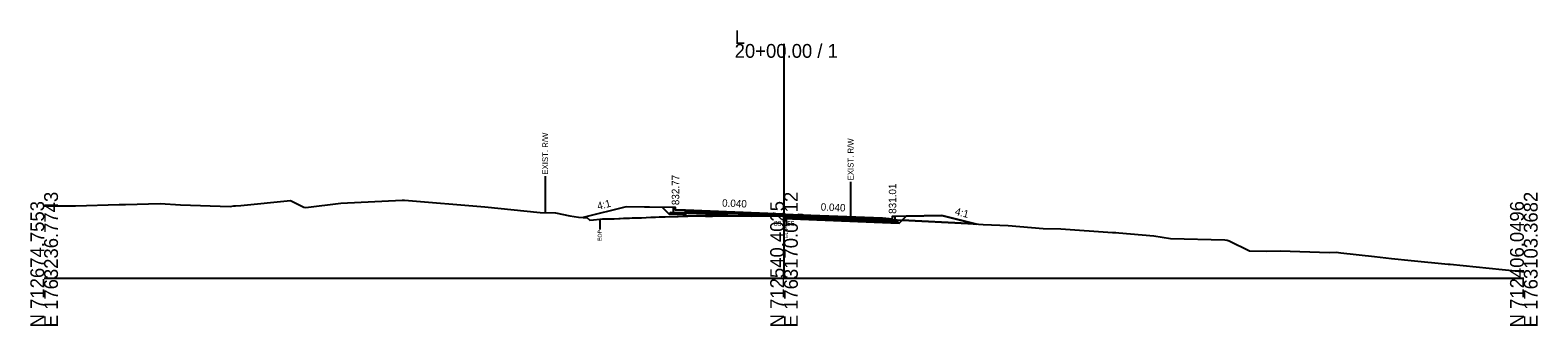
# Model space of a CAD drawing. Extents: x -26 to 5303, y -10 to 9578.
# Drawn here: x 997.2 to 1302.8, y -9.7 to 50.2 of the extents above; entities that cross this region are included whole.
import ezdxf

# ---------------------------------------------------------------- set-up
doc = ezdxf.new("R2010")
doc.units = 0
for name, color, linetype in [('Default', 7, 'Continuous'), ('Exist CMT Pavement', 7, 'Continuous'), ('Exist Cross Section Cell', 7, 'Continuous'), ('Exist XS Ground Line', 7, 'Continuous'), ('Old_Level_10', 7, 'Continuous'), ('Old_Level_3', 7, 'Continuous'), ('Prop CMT Conc Surface', 7, 'Continuous'), ('Prop CMT Concrete Structures', 7, 'Continuous'), ('Prop CMT Pvmt Course 1', 7, 'Continuous'), ('Prop CMT Pvmt Course 1 CG', 7, 'Continuous'), ('Prop CMT Pvmt Course 2', 7, 'Continuous'), ('Prop CMT Pvmt Course 3', 7, 'Continuous'), ('Prop CMT Pvmt Surface', 7, 'Continuous'), ('Prop CMT Slope Grass', 7, 'Continuous'), ('Prop CMT Subgrade Earthwork', 7, 'Continuous'), ('Prop XS Earthwork Shape', 7, 'Continuous'), ('Prop XS Hydro Elevations', 7, 'Continuous'), ('Prop XS SE Text', 7, 'Continuous'), ('Prop XS Side Slope Text', 7, 'Continuous'), ('Prop XS Wedging', 7, 'Continuous')]:
    doc.layers.add(name, color=color, linetype=linetype)

msp = doc.modelspace()

# ---------------------------------------------------------------- linework, layer by layer
at = {"layer": 'Exist CMT Pavement'}
msp.add_lwpolyline([(1130, 12.53), (1130.48, 12.54), (1132.31, 12.58), (1134.1, 12.56), (1135.1, 12.54), (1135.43, 12.56), (1137.44, 12.62), (1138.15, 12.6), (1138.52, 12.61), (1139.23, 12.61), (1139.77, 12.61), (1140.68, 12.6), (1141.73, 12.59), (1142.89, 12.58), (1143.47, 12.57), (1145.19, 12.6), (1146.26, 12.6), (1147.35, 12.6), (1149.05, 12.58), (1150, 12.55)], dxfattribs=at)
at = {"layer": 'Exist Cross Section Cell'}
for p, q in [((1150, 0), (1150, 47.44)), ((1000, 0), (1150, 0)), ((1150, 0), (1300, 0))]:
    msp.add_line(p, q, dxfattribs=at)
at = {"layer": 'Exist XS Ground Line'}
msp.add_lwpolyline([(1000, 14.61), (1006.38, 14.61), (1015.23, 14.91), (1016.47, 14.93), (1023.52, 15.09), (1027.64, 14.83), (1037.72, 14.52), (1038.44, 14.61), (1038.8, 14.65), (1039.87, 14.69), (1049.97, 15.7), (1052.68, 14.33), (1053.03, 14.32), (1060.18, 15.19), (1072.59, 15.81), (1073.04, 15.81), (1089.31, 14.41), (1100.55, 13.28), (1103.67, 13.22), (1106.55, 12.63), (1108.32, 12.34), (1109.62, 12.28), (1110, 12.29), (1110.64, 11.76), (1111.4, 11.82), (1112.63, 11.92), (1113.17, 11.98), (1114.06, 12), (1114.92, 12.02), (1115.56, 12.03), (1117.47, 12.11), (1118.35, 12.14), (1119.24, 12.17), (1121.14, 12.22), (1123.02, 12.31), (1123.93, 12.36), (1124.66, 12.38), (1125.9, 12.42), (1126.72, 12.45), (1128.56, 12.5), (1129.52, 12.52), (1130.48, 12.54), (1132.31, 12.58), (1134.1, 12.56), (1135.1, 12.54), (1135.51, 12.55), (1136.8, 12.59), (1137.39, 12.61), (1138.15, 12.6), (1138.46, 12.61), (1139.23, 12.61), (1139.77, 12.61), (1140.68, 12.6), (1141.03, 12.6), (1141.73, 12.59), (1143.47, 12.57), (1145.19, 12.6), (1146.26, 12.6), (1147.35, 12.6), (1149.05, 12.58), (1150, 12.55), (1150.44, 12.54), (1151.13, 12.53), (1152.37, 12.5), (1153.02, 12.89), (1153.4, 12.86), (1155.07, 12.7), (1162.59, 12.22), (1165.78, 11.78), (1167.1, 11.87), (1172.6, 11.8), (1172.93, 11.78), (1187.24, 11.05), (1188.32, 10.99), (1188.72, 10.97), (1189.43, 10.92), (1190.38, 10.87), (1195.42, 10.66), (1202.56, 10.07), (1206.1, 9.95), (1216.63, 9.24), (1217.27, 9.2), (1217.91, 9.15), (1224.95, 8.58), (1228.35, 8.01), (1239.41, 7.72), (1239.88, 7.69), (1240.23, 7.57), (1244.39, 5.52), (1247.76, 5.42), (1250.59, 5.5), (1260.61, 5.16), (1261.94, 5.23), (1262.89, 5.12), (1269.71, 4.35), (1273.17, 3.98), (1277.18, 3.54), (1284.64, 2.83), (1285.09, 2.79), (1295.59, 1.71), (1299.57, 1.31), (1300, 1.28)], dxfattribs=at)
at = {"layer": 'Old_Level_10'}
for p, q in [((1101.57, 20.66), (1101.57, 13.26)), ((1163.5, 19.5), (1163.5, 12.09)), ((1150.44, 12.54), (1150.44, 10.49)), ((1112.63, 11.92), (1112.63, 9.86))]:
    msp.add_line(p, q, dxfattribs=at)
at = {"layer": 'Prop CMT Conc Surface'}
for points in [[(1128, 13.77), (1128, 14.27), (1127.5, 14.27)], [(1130, 13.77), (1128, 13.77)], [(1172, 12.01), (1172, 12.51), (1172.5, 12.51)], [(1170, 12.17), (1172, 12.01)]]:
    msp.add_lwpolyline(points, dxfattribs=at)
at = {"layer": 'Prop CMT Concrete Structures'}
for points in [[(1130, 13.77), (1128, 13.77), (1128, 14.27), (1127.5, 14.27)], [(1127.5, 14.27), (1127.5, 13.29), (1130, 13.19)], [(1130, 13.19), (1130, 13.77)], [(1170, 12.17), (1172, 12.01), (1172, 12.51), (1172.5, 12.51)], [(1172.5, 12.51), (1172.5, 11.49), (1170, 11.59)], [(1170, 11.59), (1170, 12.17)]]:
    msp.add_lwpolyline(points, dxfattribs=at)
at = {"layer": 'Prop CMT Pvmt Course 1'}
for points in [[(1150, 12.97), (1130, 13.77)], [(1130, 13.77), (1130, 13.52)], [(1130, 13.52), (1150, 12.72)], [(1150, 12.72), (1150, 12.97)], [(1150, 12.97), (1170, 12.17)], [(1150, 12.72), (1150, 12.72), (1150, 12.72)], [(1170, 11.92), (1150, 12.72)], [(1150, 12.72), (1150, 12.72), (1150, 12.72), (1150, 12.72), (1150, 12.72)], [(1170, 12.17), (1170, 11.92)]]:
    msp.add_lwpolyline(points, dxfattribs=at)
at = {"layer": 'Prop CMT Pvmt Course 1 CG'}
for points in [[(1130, 13.19), (1127, 13.31), (1126.68, 12.99)], [(1126.68, 12.99), (1130, 12.86)], [(1130, 12.86), (1130, 13.19)], [(1170, 11.59), (1173, 11.47), (1173.35, 11.12)], [(1170, 11.26), (1170, 11.59)], [(1173.35, 11.12), (1170, 11.26)]]:
    msp.add_lwpolyline(points, dxfattribs=at)
at = {"layer": 'Prop CMT Pvmt Course 2'}
for points in [[(1130, 13.52), (1130, 13.19)], [(1150, 12.39), (1150, 12.72)], [(1150, 12.72), (1170, 11.92)], [(1170, 11.59), (1150, 12.39)], [(1170, 11.92), (1170, 11.59)]]:
    msp.add_lwpolyline(points, dxfattribs=at)
at = {"layer": 'Prop CMT Pvmt Course 3'}
for points in [[(1130, 13.19), (1130, 12.86)], [(1150, 12.39), (1170, 11.59)], [(1150, 12.06), (1150, 12.39)], [(1170, 11.26), (1150, 12.06)], [(1170, 11.59), (1170, 11.26)]]:
    msp.add_lwpolyline(points, dxfattribs=at)
at = {"layer": 'Prop CMT Pvmt Surface'}
for points in [[(1150, 12.97), (1130, 13.77)], [(1150, 12.97), (1170, 12.17)]]:
    msp.add_lwpolyline(points, dxfattribs=at)
at = {"layer": 'Prop CMT Slope Grass'}
for points in [[(1127.5, 14.27), (1118, 14.46), (1109.3, 12.29)], [(1172.5, 12.51), (1182, 12.7), (1189.04, 10.94)]]:
    msp.add_lwpolyline(points, dxfattribs=at)
at = {"layer": 'Prop CMT Subgrade Earthwork'}
for p, q in [((1130, 12.86), (1130, 12.53)), ((1150, 12.55), (1150, 12.06))]:
    msp.add_line(p, q, dxfattribs=at)
for points in [[(1130, 12.86), (1126.68, 12.99), (1125.35, 14.32)], [(1170, 11.26), (1173.35, 11.12), (1174.78, 12.56)], [(1150, 12.06), (1170, 11.26)]]:
    msp.add_lwpolyline(points, dxfattribs=at)
at = {"layer": 'Prop XS Earthwork Shape'}
for points in [[(1129.52, 12.52), (1130, 12.53), (1130, 12.86), (1126.68, 12.99), (1125.35, 14.32), (1118, 14.46), (1109.3, 12.29), (1109.62, 12.28), (1110, 12.29), (1110.64, 11.76), (1111.4, 11.82), (1112.63, 11.92), (1113.17, 11.98), (1114.06, 12), (1114.92, 12.02), (1115.56, 12.03), (1116.78, 12.07), (1118.65, 12.15), (1119.24, 12.17), (1121.14, 12.22), (1123.02, 12.31), (1123.93, 12.36), (1124.66, 12.38), (1125.9, 12.42), (1126.72, 12.45), (1128.56, 12.5)], [(1165.78, 11.78), (1167.1, 11.87), (1172.93, 11.78), (1173.95, 11.73), (1173.35, 11.12), (1170, 11.26), (1150, 12.06), (1150, 12.55), (1150.44, 12.54), (1151.13, 12.53), (1152.37, 12.5), (1152.96, 12.86), (1153.75, 12.82), (1155.07, 12.7), (1162.59, 12.22)], [(1162.59, 12.22), (1165.78, 11.78), (1167.1, 11.87), (1172.93, 11.78), (1173.95, 11.73), (1173.35, 11.12), (1170, 11.26), (1150, 12.06), (1150, 12.55), (1150.44, 12.54), (1151.13, 12.53), (1152.37, 12.5), (1152.96, 12.86), (1153.75, 12.82), (1155.07, 12.7)], [(1152.96, 12.86), (1153.02, 12.89), (1153.4, 12.86), (1153.75, 12.82)], [(1174.78, 12.56), (1182, 12.7), (1189.04, 10.94), (1188.72, 10.97), (1188.32, 10.99), (1187.24, 11.05), (1173.95, 11.73)], [(1188.32, 10.99), (1188.72, 10.97), (1189.04, 10.94), (1182, 12.7), (1174.78, 12.56), (1173.95, 11.73), (1187.24, 11.05)]]:
    msp.add_lwpolyline(points, close=True, dxfattribs=at)
at = {"layer": 'Prop XS Wedging'}
for points in [[(1130, 12.53), (1130, 13.52), (1130.48, 13.51), (1132.31, 13.43), (1134.11, 13.36), (1135.1, 13.32), (1135.43, 13.31), (1137.44, 13.23), (1138.14, 13.2), (1138.52, 13.18), (1139.23, 13.16), (1139.77, 13.13), (1140.68, 13.1), (1141.73, 13.06), (1142.89, 13.01), (1143.47, 12.99), (1145.19, 12.92), (1146.26, 12.87), (1147.35, 12.83), (1149.05, 12.76), (1150, 12.72), (1150.44, 12.71), (1150.44, 12.54), (1150, 12.55), (1149.05, 12.58), (1147.35, 12.6), (1146.26, 12.6), (1145.19, 12.6), (1143.47, 12.57), (1142.89, 12.58), (1141.73, 12.59), (1140.68, 12.6), (1139.77, 12.61), (1139.23, 12.61), (1138.52, 12.61), (1138.14, 12.6), (1137.44, 12.62), (1135.43, 12.56), (1135.1, 12.54), (1134.11, 12.56), (1132.31, 12.58), (1130.48, 12.54)], [(1130, 12.53), (1130, 13.52), (1130.48, 13.51), (1132.31, 13.43), (1134.11, 13.36), (1135.1, 13.32), (1135.43, 13.31), (1137.44, 13.23), (1138.14, 13.2), (1138.52, 13.18), (1139.23, 13.16), (1139.77, 13.13), (1140.68, 13.1), (1141.73, 13.06), (1142.89, 13.01), (1143.47, 12.99), (1145.19, 12.92), (1146.26, 12.87), (1147.35, 12.83), (1148.22, 12.8), (1148.43, 12.58), (1147.35, 12.6), (1146.26, 12.6), (1145.19, 12.6), (1143.47, 12.57), (1142.89, 12.58), (1141.73, 12.59), (1140.68, 12.6), (1139.77, 12.61), (1139.23, 12.61), (1138.52, 12.61), (1138.14, 12.6), (1137.44, 12.62), (1135.43, 12.56), (1135.1, 12.54), (1134.11, 12.56), (1132.31, 12.58), (1130.48, 12.54)], [(1130, 12.53), (1130, 13.2), (1130.48, 13.18), (1132.31, 13.1), (1134.11, 13.03), (1135.1, 12.99), (1135.43, 12.98), (1137.44, 12.9), (1138.14, 12.87), (1138.41, 12.86), (1138.66, 12.61), (1138.14, 12.6), (1137.44, 12.62), (1135.43, 12.56), (1135.1, 12.54), (1134.11, 12.56), (1132.31, 12.58), (1130.48, 12.54)]]:
    msp.add_lwpolyline(points, close=True, dxfattribs=at)

# ---------------------------------------------------------------- texts
at = {"layer": 'Default'}
msp.add_text('-', height=0.0001, dxfattribs=at).set_placement((1000, 0))
at = {"layer": 'Exist Cross Section Cell'}
for s, p in [('L', (1140, 47.44)), ('20+00.00 / 1', (1140, 44.64))]:
    msp.add_text(s, height=2.8, dxfattribs=at).set_placement(p)
for s, p in [('N 712674.7553', (1000, -10)), ('E 1763236.7743', (1002.8, -10)), ('N 712540.4025', (1150, -10)), ('E 1763170.0712', (1152.8, -10)), ('N 712406.0496', (1300, -10)), ('E 1763103.3682', (1302.8, -10))]:
    msp.add_text(s, height=2.8, rotation=90, dxfattribs=at).set_placement(p)
at = {"layer": 'Old_Level_10'}
for s, height, p in [('EXIST. R/W', 1.181, (1102.16, 20.96)), ('EXIST. R/W', 1.181, (1164.09, 19.8)), ('EOP', 0.787, (1113.03, 7.47)), ('EOP', 0.787, (1150.83, 8.09))]:
    msp.add_text(s, height=height, rotation=90, dxfattribs=at).set_placement(p)
at = {"layer": 'Old_Level_3'}
msp.add_text('831.55', height=1, dxfattribs=at).set_placement((1147.95, 10.55))
at = {"layer": 'Prop XS Hydro Elevations'}
for s, p in [('832.77', (1128.75, 14.77)), ('831.01', (1172.75, 13.01))]:
    msp.add_text(s, height=1.5, rotation=90, dxfattribs=at).set_placement(p)
at = {"layer": 'Prop XS SE Text'}
for p in [(1137.42, 14.48), (1157.42, 13.68)]:
    msp.add_text('0.040', height=1.5, rotation=357.7094, dxfattribs=at).set_placement(p)
at = {"layer": 'Prop XS Side Slope Text'}
for rotation, p in [(14.0362, (1112.32, 13.82)), (345.9638, (1184.55, 12.84))]:
    msp.add_text('4:1', height=1.5, rotation=rotation, dxfattribs=at).set_placement(p)

doc.saveas('drawing.dxf')
